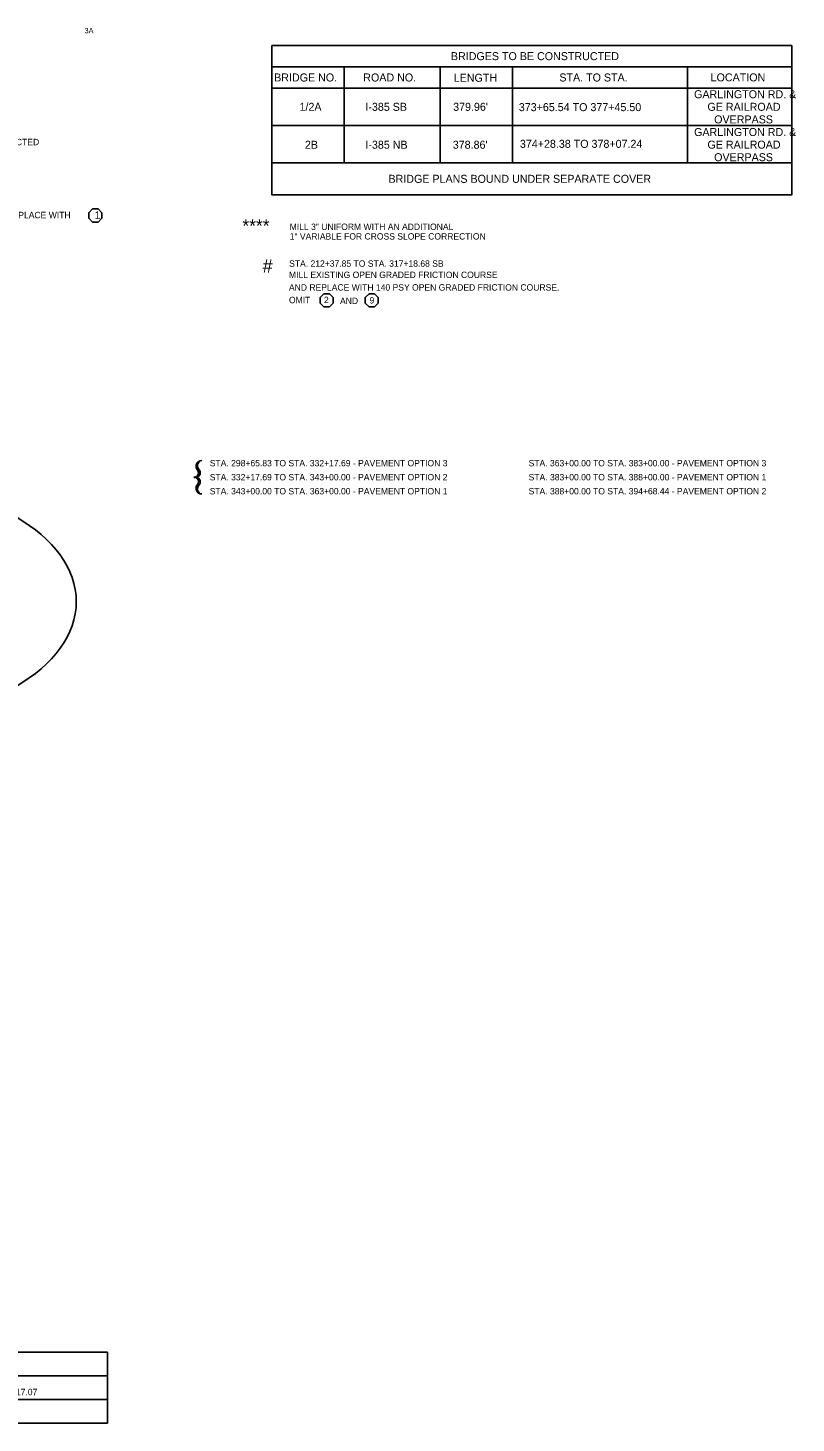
# Model space of a CAD drawing. Extents: x 4832 to 5477, y 4935 to 5220.
# Drawn here: x 5332.6 to 5476.7, y 4953.3 to 5214.8 of the extents above; entities that cross this region are included whole.
import ezdxf

# ---------------------------------------------------------------- set-up
doc = ezdxf.new("R2010")
doc.units = 0
for name, color, linetype in [('Level 3', 7, 'Continuous'), ('RD_SHT_TX', 7, 'Continuous'), ('RD_TX_TitleSht', 7, 'Continuous'), ('RD_TX_TypSect', 7, 'Continuous'), ('typical_on', 7, 'Continuous')]:
    doc.layers.add(name, color=color, linetype=linetype)

# ---------------------------------------------------------------- blocks, each defined once
blk = doc.blocks.new('BRACKET')
at = {"layer": 'RD_TX_TypSect'}
for p, q in [((0.13, 0.01), (0, 0)), ((0.13, 0.01), (0, 0)), ((0.15, -0.02), (0, 0)), ((0, 0), (0.15, -0.02))]:
    blk.add_line(p, q, dxfattribs=at)
for centre, radius, start, end in [((1.51, 2.04), 1.09, 89.433, 224.7127), ((1.51, 2.04), 1.09, 106.8416, 224.7127), ((1.81, 2.18), 1.09, 124.5318, 224.2806), ((1.81, 2.18), 1.09, 124.5318, 224.2806), ((0.05, 0.83), 0.822, 275.644, 32.5641), ((0.05, 0.83), 0.822, 275.644, 32.5641), ((0.33, 0.86), 0.9, 286.1681, 38.6042), ((0.33, 0.86), 0.9, 286.1681, 38.6042), ((0.05, -0.83), 0.822, 327.4359, 82.4975), ((0.05, -0.83), 0.822, 327.4359, 82.4975), ((1.51, -2.04), 1.09, 135.2873, 270.567), ((1.51, -2.04), 1.09, 135.2873, 253.1584), ((0.33, -0.87), 0.9, 321.3958, 73.8319), ((0.33, -0.87), 0.9, 321.3958, 73.8319), ((1.81, -2.19), 1.09, 135.7194, 235.4682), ((1.81, -2.19), 1.09, 135.7194, 235.4682)]:
    blk.add_arc(centre, radius, start, end, dxfattribs=at)

msp = doc.modelspace()

# ---------------------------------------------------------------- linework, layer by layer
at = {"layer": 'Level 3'}
for p, q in [((5378.34, 5189.55), (5378.34, 5211.55)), ((5378.34, 5211.55), (5475.94, 5211.55)), ((5475.94, 5189.55), (5475.94, 5211.55)), ((5378.34, 5207.55), (5475.94, 5207.55)), ((5409.94, 5189.55), (5409.94, 5207.55)), ((5423.54, 5189.55), (5423.54, 5207.55)), ((5456.34, 5189.55), (5456.34, 5207.55)), ((5378.34, 5203.55), (5475.94, 5203.55)), ((5378.34, 5196.55), (5475.94, 5196.55)), ((5378.34, 5189.55), (5475.94, 5189.55))]:
    msp.add_line(p, q, dxfattribs=at)
msp.add_lwpolyline([(5378.34, 5189.55), (5475.94, 5189.55), (5475.94, 5183.55), (5378.34, 5183.55)], close=True, dxfattribs=at)
at = {"layer": 'RD_TX_TitleSht'}
msp.add_line((5391.94, 5207.55), (5391.94, 5189.55), dxfattribs=at)
at = {"layer": 'RD_TX_TypSect'}
for p, q in [((5268.91, 4966.56), (5347.56, 4966.56)), ((5347.56, 4966.56), (5347.56, 4953.25)), ((5268.91, 4962.12), (5347.56, 4962.12)), ((5268.91, 4957.69), (5347.56, 4957.69)), ((5268.91, 4953.25), (5347.56, 4953.25))]:
    msp.add_line(p, q, dxfattribs=at)
msp.add_ellipse((5303.06, 5107.27), major_axis=(38.62, 0), ratio=0.582122, dxfattribs=at)
at = {"layer": 'typical_on'}
for points in [[(5346.48, 5180.18), (5346.48, 5179.16), (5345.76, 5178.44), (5344.74, 5178.44), (5344.01, 5179.16), (5344.01, 5180.18), (5344.74, 5180.9), (5345.76, 5180.9)], [(5389.89, 5164.27), (5389.89, 5163.25), (5389.17, 5162.53), (5388.15, 5162.53), (5387.42, 5163.25), (5387.42, 5164.27), (5388.15, 5165), (5389.17, 5165)], [(5398.34, 5164.27), (5398.34, 5163.25), (5397.62, 5162.53), (5396.6, 5162.53), (5395.87, 5163.25), (5395.87, 5164.27), (5396.6, 5165), (5397.62, 5165)]]:
    msp.add_lwpolyline(points, close=True, dxfattribs=at)

# ---------------------------------------------------------------- block references
at = {"layer": 'RD_TX_TypSect'}
msp.add_blockref('BRACKET', (5363.72, 5130.59), dxfattribs=at)

# ---------------------------------------------------------------- texts
at = {"layer": 'Level 3'}
for s, p in [('BRIDGES TO BE CONSTRUCTED', (5411.96, 5208.8)), ('BRIDGE NO.', (5378.8, 5204.8)), ('ROAD NO.', (5395.52, 5204.8)), ('LENGTH', (5412.49, 5204.75)), ('STA. TO STA.', (5432.31, 5204.8)), ('LOCATION', (5460.69, 5204.82)), ('GARLINGTON RD. & ', (5457.59, 5201.66)), ('1/2A', (5383.56, 5199.3)), ('I-385 SB', (5395.92, 5199.3)), ("379.96'", (5412.38, 5199.3)), ('373+65.54 TO 377+45.50', (5424.7, 5199.24)), ('GE RAILROAD', (5460.1, 5199.3)), ('OVERPASS', (5461.35, 5196.94)), ('GARLINGTON RD. & ', (5457.59, 5194.57)), ('2B', (5384.57, 5192.19)), ('I-385 NB', (5395.92, 5192.19)), ("378.86'", (5412.31, 5192.19)), ('374+28.38 TO 378+07.24', (5424.91, 5192.36)), ('GE RAILROAD', (5460.1, 5192.21)), ('OVERPASS', (5461.35, 5189.85)), ('BRIDGE PLANS BOUND UNDER SEPARATE COVER', (5400.25, 5185.8))]:
    msp.add_text(s, height=1.5, dxfattribs=at).set_placement(p)
at = {"layer": 'RD_SHT_TX'}
msp.add_text('3A', height=1, rotation=0.0001, dxfattribs=at).set_placement((5343.22, 5213.83))
at = {"layer": 'RD_TX_TypSect'}
msp.add_text("ADD 3.5' WHERE GUARDRAIL IS ERECTED ", height=1.1999, rotation=360, dxfattribs=at).set_placement((5302.05, 5192.85))
for s, height, p in [('MICRO MILL EXISTING OGFC AND REPLACE WITH', 1.2001, (5301.91, 5179.16)), ('1', 1.45, (5345.12, 5179.01)), ('****', 2.443, (5372.85, 5176.52)), ('MILL 3" UNIFORM WITH AN ADDITIONAL', 1.1999, (5381.72, 5176.96)), ('1" VARIABLE FOR CROSS SLOPE CORRECTION', 1.1999, (5381.72, 5175.16)), ('#', 2.5, (5376.65, 5168.96)), ('STA. 212+37.85 TO STA. 317+18.68 SB', 1.1999, (5381.61, 5170.06)), ('MILL EXISTING OPEN GRADED FRICTION COURSE', 1.1999, (5381.58, 5167.95)), ('AND REPLACE WITH 140 PSY OPEN GRADED FRICTION COURSE.', 1.1999, (5381.58, 5165.59)), ('OMIT', 1.2, (5381.58, 5163.23)), ('2', 1.2, (5388.15, 5163.25)), ('AND', 1.2, (5391.16, 5163.06)), ('9', 1.2, (5396.69, 5163.17)), ('STA. 298+65.83 TO STA. 332+17.69 - PAVEMENT OPTION 3', 1.2, (5366.72, 5132.64)), ('STA. 363+00.00 TO STA. 383+00.00 - PAVEMENT OPTION 3', 1.2, (5426.54, 5132.64)), ('STA. 332+17.69 TO STA. 343+00.00 - PAVEMENT OPTION 2', 1.2, (5366.72, 5130.01)), ('STA. 383+00.00 TO STA. 388+00.00 - PAVEMENT OPTION 1', 1.2, (5426.54, 5130.01)), ('STA. 343+00.00 TO STA. 363+00.00 - PAVEMENT OPTION 1', 1.2, (5366.72, 5127.38)), ('STA. 388+00.00 TO STA. 394+68.44 - PAVEMENT OPTION 2', 1.2, (5426.54, 5127.38)), ('AND NEW SHOULDER SOUTHBOUND FROM STA. 303+89.49 TO STA. 332+17.07', 1.2, (5273.55, 4958.48))]:
    msp.add_text(s, height=height, dxfattribs=at).set_placement(p)

doc.saveas('drawing.dxf')
